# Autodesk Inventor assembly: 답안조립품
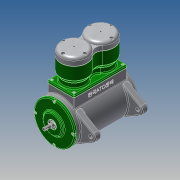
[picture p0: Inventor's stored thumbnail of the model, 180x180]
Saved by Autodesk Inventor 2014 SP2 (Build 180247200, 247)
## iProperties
Created: 2019-08
Part Number: 답안조립품
Document SubType Name: Assembly
Designer: kb542-10
Author: kb542-10
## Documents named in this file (18)
- C:\Users\kb542-10\Desktop\390804V1048\답안조립품.iam
- C:\Users\kb542-10\Desktop\390804V1048\본체.ipt
- C:\Users\kb542-10\Desktop\390804V1048\앞커버.ipt
- C:\Users\kb542-10\Desktop\390804V1048\크랭크축.ipt
- C:\Users\kb542-10\Desktop\390804V1048\베어링 12 x 28 x 8.ipt
- C:\Users\kb542-10\Desktop\390804V1048\오일 실 12 25 7.ipt
- C:\Users\kb542-10\Desktop\390804V1048\실린더 개스킷.ipt
- C:\Users\kb542-10\Desktop\390804V1048\실린더.ipt
- C:\Users\kb542-10\Desktop\390804V1048\피스톤.ipt
- C:\Users\kb542-10\Desktop\390804V1048\피스톤핀.ipt
- C:\Users\kb542-10\Desktop\390804V1048\커넥팅로드.ipt
- C:\Users\kb542-10\Desktop\390804V1048\커넥팅로드 엔드.ipt
- C:\Users\kb542-10\Desktop\390804V1048\육각 머리 볼트 M4 x 16.ipt
- C:\Users\kb542-10\Desktop\390804V1048\너트 M4.ipt
- C:\Users\kb542-10\Desktop\390804V1048\실린더헤드 개스킷.ipt
- C:\Users\kb542-10\Desktop\390804V1048\실린더헤드.ipt
- C:\Users\kb542-10\Desktop\390804V1048\볼트 M4 x 8.ipt
- C:\Users\kb542-10\Desktop\390804V1048\볼트 M5 x 20.ipt
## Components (4 placed, 2 different names)
1. 피스톤:1
2. 피스톤:2
3. 피스톤핀:1
4. 피스톤핀:2
